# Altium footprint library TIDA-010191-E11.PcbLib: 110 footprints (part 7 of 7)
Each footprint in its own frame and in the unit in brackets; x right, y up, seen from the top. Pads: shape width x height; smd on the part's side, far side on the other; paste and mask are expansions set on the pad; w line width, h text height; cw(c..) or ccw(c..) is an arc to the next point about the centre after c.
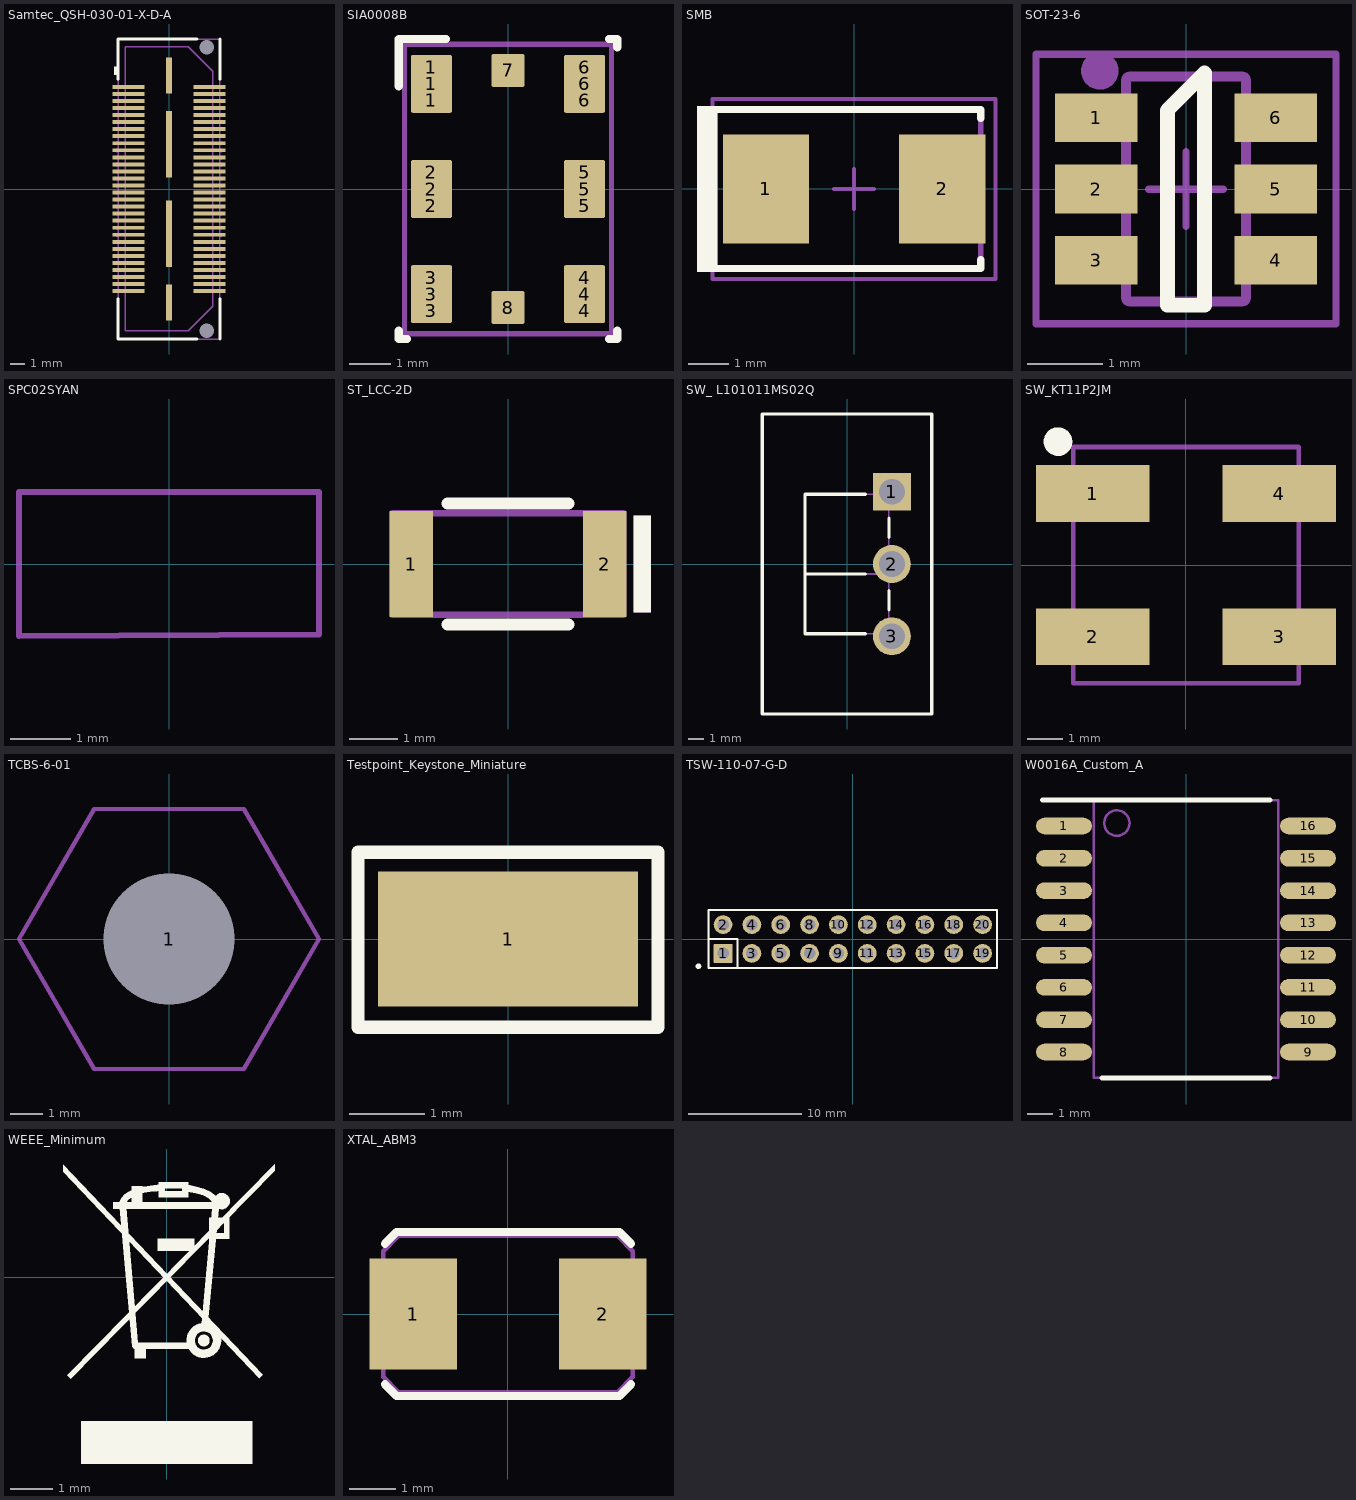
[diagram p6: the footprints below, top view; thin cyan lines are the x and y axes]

## Samtec_QSH-030-01-X-D-A [mm] "Receptacle, 0.5 mm, 30x2, TH"
height 3.327
pads (66):
  rect 2.27x0.279 smd: 1(-2.865,7.25) 2(2.865,7.25) 3(-2.865,6.75) 4(2.865,6.75) 5(-2.865,6.25) 6(2.865,6.25) 7(-2.865,5.75) 8(2.865,5.75) 9(-2.865,5.25) 10(2.865,5.25) 11(-2.865,4.75) 12(2.865,4.75) 13(-2.865,4.25) 14(2.865,4.25) 15(-2.865,3.75) 16(2.865,3.75) 17(-2.865,3.25) 18(2.865,3.25) 19(-2.865,2.75) 20(2.865,2.75) 21(-2.865,2.25) 22(2.865,2.25) 23(-2.865,1.75) 24(2.865,1.75) 25(-2.865,1.25) 26(2.865,1.25) 27(-2.865,0.75) 28(2.865,0.75) 29(-2.865,0.25) 30(2.865,0.25) 31(-2.865,-0.25) 32(2.865,-0.25) 33(-2.865,-0.75) 34(2.865,-0.75) 35(-2.865,-1.25) 36(2.865,-1.25) 37(-2.865,-1.75) 38(2.865,-1.75) 39(-2.865,-2.25) 40(2.865,-2.25) 41(-2.865,-2.75) 42(2.865,-2.75) 43(-2.865,-3.25) 44(2.865,-3.25) 45(-2.865,-3.75) 46(2.865,-3.75) 47(-2.865,-4.25) 48(2.865,-4.25) 49(-2.865,-4.75) 50(2.865,-4.75) 51(-2.865,-5.25) 52(2.865,-5.25) 53(-2.865,-5.75) 54(2.865,-5.75) 55(-2.865,-6.25) 56(2.865,-6.25) 57(-2.865,-6.75) 58(2.865,-6.75) 59(-2.865,-7.25) 60(2.865,-7.25)
  round 0 hole 1.02 unplated: MH1(2.67,10.065) MH2(2.67,-10.065)
  rect 0.43x2.54 smd: MP1(0,8.065) MP4(0,-8.065)
  rect 0.43x4.7 smd: MP2(0,3.175) MP3(0,-3.175)
Top Overlay:
  rectangle: -3.9,8.1 -3.62,8.7
  lines w0.2: -3.62,-7.789 -3.62,-10.655 2,-10.655 ; -3.62,7.789 -3.62,10.655 2,10.655 ; 3.62,-10.655 3.62,-7.789 ; 3.62,7.789 3.62,10.655
Mechanical 5:
  drawing of 190 lines, arcs and shapes, not listed
  text ".Designator" at -1.524,-0.508 h1.02
3D body "Samtec-QSH-030-01-L-D-A.stp": height 3.25, standoff -0.75, extent -3.746,-10.636 3.747,10.674

## SIA0008B [mm] "SIP 8-Leads, Body 5x7mm"
height 1.1
pads (20):
  rrect50% 1x0.6 on Top Paste: 1(-1.85,2.14) 1(-1.85,2.94) 2(-1.85,-0.4) 2(-1.85,0.4) 3(-1.85,-2.94) 3(-1.85,-2.14) 4(1.85,-2.94) 4(1.85,-2.14) 5(1.85,-0.4) 5(1.85,0.4) 6(1.85,2.14) 6(1.85,2.94)
  rrect10% 1x1.4 smd paste-0.5: 1(-1.85,2.54) 2(-1.85,0) 3(-1.85,-2.54) 4(1.85,-2.54) 5(1.85,0) 6(1.85,2.54)
  rrect12% 0.8x0.8 smd: 7(0,2.865) 8(0,-2.865)
Top Overlay:
  lines w0.2: -2.64,-3.425 -2.64,-3.625 -2.44,-3.625 ; -2.64,2.485 -2.64,3.625 -1.5,3.625 ; 2.44,-3.625 2.64,-3.625 2.64,-3.425 ; 2.44,3.625 2.64,3.625 2.64,3.425
Mechanical 5:
  circle w0.1: c-1.84,2.54 r0.25
  lines w0.127: -2.5,-3.5 2.5,-3.5 2.5,3.5 -2.5,3.5 -2.5,-3.5
  text ".Designator" at -1.4,0 h0.76
3D body: height 1.1, standoff 0, extent -2.564,-3.564 2.564,3.564
3D body: height 1.13, standoff 0, extent -2.156,2.224 -1.525,2.856

## SMB [mm] "Molded Diode, 2-Leads, Body 5.4x3.6mm, IPC Medium Density, based on OnSemi component dimensions"
height 2.65
pads (2):
  rect 2.159x2.743 smd: 1(-2.21,0) 2(2.21,0)
Top Overlay:
  rectangle: -3.937,-2.083 -3.429,2.083
  lines w0.178: -3.607,-1.994 3.175,-1.994 3.175,-1.765 ; -3.607,1.994 3.175,1.994 3.175,1.765
Mechanical 5:
  rectangle: -3.937,-2.083 -3.429,2.083
  lines w0.127: -3.607,-1.994 3.175,-1.994 3.175,-1.765 3.175,1.765 3.175,1.994 -3.607,1.994
  text ".Designator" at -2.311,-0.508 h1.02
Mechanical 15:
  lines w0.1: -0.5,0 0.5,0 ; 0,-0.5 0,0.5 ; -3.55,-2.25 -3.55,2.25 3.55,2.25 3.55,-2.25 -3.55,-2.25
3D body "SMB_nominal.stp": height 2.32, standoff 0.02, extent -2.7,-1.8 2.7,1.8

## SOT-23-6 [mm] "SOT23, 6-Leads, Body 3.0x1.7mm, Pitch 0.95mm, Lead Span 2.9mm, IPC Medium Density"
height 1
pads (6):
  rect 1.1x0.65 smd: 1(-1.2,0.95) 2(-1.2,0) 3(-1.2,-0.95) 4(1.2,-0.95) 5(1.2,0) 6(1.2,0.95)
Top Overlay:
  lines w0.2: -0.25,-1.55 -0.25,1.05 0.25,1.55 0.25,-1.55 -0.25,-1.55
Mechanical 5:
  circle w0.25: c-1.15,1.575 r0.125
  lines w0.127: -0.8,-1.45 ccw(c-0.75,-1.45) -0.75,-1.5 ; -0.8,-1.45 -0.8,-1.45 ; -0.8,-1.45 -0.8,-1.2 ; -0.8,-1.2 -0.8,-0.7 ; -0.8,-1.2 -0.812,-1.2 -1.109,-1.2 -1.166,-1.2 -1.265,-1.2 -1.5,-1.2 -1.5,-0.7 -1.265,-0.7 -1.166,-0.7 -1.109,-0.7 -0.812,-0.7 -0.8,-0.7 ; -0.8,-0.7 -0.8,-0.25 ; -0.8,-0.25 -0.8,0.25 ; -0.8,-0.25 -0.812,-0.25 -1.109,-0.25 -1.166,-0.25 -1.265,-0.25 -1.5,-0.25 -1.5,0.25 -1.265,0.25 -1.166,0.25 -1.109,0.25 -0.812,0.25 -0.8,0.25 ; -0.8,0.25 -0.8,0.7 ; -0.8,0.7 -0.8,1.2 ; -0.8,0.7 -0.812,0.7 -1.109,0.7 -1.166,0.7 -1.265,0.7 -1.5,0.7 -1.5,1.2 -1.265,1.2 -1.166,1.2 -1.109,1.2 -0.812,1.2 -0.8,1.2 ; -0.8,1.2 -0.8,1.45 ; -0.8,1.45 cw(c-0.75,1.45) -0.75,1.5 ; -0.8,1.45 -0.8,1.45 ; -0.75,-1.5 0.75,-1.5 ; -0.75,-1.5 -0.75,-1.5 ; -0.75,1.5 -0.75,1.5 ; -0.75,1.5 0.75,1.5 ; 0.75,-1.5 ccw(c0.75,-1.45) 0.8,-1.45 ; 0.75,-1.5 0.75,-1.5 ; 0.75,1.5 cw(c0.75,1.45) 0.8,1.45 ; 0.75,1.5 0.75,1.5 ; 0.8,-1.45 0.8,-1.45 ; 0.8,-1.45 0.8,-1.2 ; 0.8,-1.2 0.812,-1.2 1.109,-1.2 1.166,-1.2 1.265,-1.2 1.5,-1.2 1.5,-0.7 1.265,-0.7 1.166,-0.7 1.109,-0.7 0.812,-0.7 0.8,-0.7 ; 0.8,-1.2 0.8,-0.7 ; 0.8,-0.7 0.8,-0.25 ; 0.8,-0.25 0.8,0.25 ; 0.8,-0.25 0.812,-0.25 1.109,-0.25 1.166,-0.25 1.265,-0.25 1.5,-0.25 1.5,0.25 1.265,0.25 1.166,0.25 1.109,0.25 0.812,0.25 0.8,0.25 ; 0.8,0.25 0.8,0.7 ; 0.8,0.7 0.812,0.7 1.109,0.7 1.166,0.7 1.265,0.7 1.5,0.7 1.5,1.2 1.265,1.2 1.166,1.2 1.109,1.2 0.812,1.2 0.8,1.2 ; 0.8,0.7 0.8,1.2 ; 0.8,1.2 0.8,1.45 ; 0.8,1.45 0.8,1.45
  text ".Designator" at -0.3,1.2 h0.64
Mechanical 15:
  lines w0.1: -0.5,0 0.5,0 ; 0,-0.5 0,0.5 ; -2,-1.8 2,-1.8 2,1.8 -2,1.8 -2,-1.8
3D body "SOT23-6.stp": height 1.3, standoff 0, extent -1.5,-1.5 1.5,1.5

## SPC02SYAN [mil] "SULLINS"
height 256
pads (1):
  round 1 on Mech3: 0(0,0)
Mechanical 5:
  lines w4: -98.43,-47.24 -98.43,47.24 98.43,47.24 98.43,-46.26 -98.43,-47.24
3D body "Sullins_SPC02SYAN.stp": height 366, standoff 110, extent -98.49,-46.99 98.51,47

## ST_LCC-2D [mm] "ST Microelectronics"
height 2.2
pads (2):
  rect 0.9x2.2 smd: 1(-2,0) 2(2,0)
Top Overlay:
  region: 2.952,1 2.952,-1 2.602,-1 2.602,1
  lines w0.254: -1.25,-1.25 1.25,-1.25 ; -1.25,1.25 1.25,1.25
Mechanical 5:
  region: 2.952,1 2.952,-1 2.602,-1 2.602,1
  lines w0.127: -2.385,-1.05 2.385,-1.05 2.385,1.05 -2.385,1.05 -2.385,-1.041 ; 2.388,-0.356 cw(c2.388,0) 2.388,0.356
  text ".Designator" at -1.803,-0.432 h0.9
3D body: height 2, standoff 1, extent -2.4,0.925 -2.375,1.05
3D body: height 2, standoff 0, extent -2.373,-1.06 2.396,1.039
3D body: height 2.2, standoff 2, extent -2,-0.8 2,0.8
3D body: height 2, standoff 0, extent -2.286,-0.991 2.311,0.965
3D body: height 2, standoff 1, extent -2.4,-1.075 -2.375,-0.95

## SW_ L101011MS02Q [mm] "SWITCH SLIDE sPST 4A PCB"
height 14.18
pads (3):
  rect 2.416x2.416 hole 1.65: 1(2.857,4.6)
  round 2.416 hole 1.65: 2(2.857,0) 3(2.857,-4.6)
Top Overlay:
  lines w0.2: -5.405,9.55 5.395,9.55 5.395,-9.55 ; -5.395,9.55 -5.395,-9.55 5.405,-9.55 ; -2.668,-0.635 1.166,-0.635 ; 1.166,-4.445 -2.668,-4.445 -2.668,4.445 1.166,4.445 ; 2.668,-2.911 2.668,-1.689 ; 2.668,1.689 2.668,2.911
Mechanical 5:
  lines w0.1: -2.668,-0.635 -2.668,-4.445 2.668,-4.445 2.668,-0.635 ; -2.668,-0.635 -2.668,4.445 2.668,4.445 2.668,-0.635 ; -2.668,-0.635 2.668,-0.635 ; -5.395,-9.55 -5.395,9.55 5.395,9.55 5.395,-9.55 -5.395,-9.55
  text ".Designator" at -2,0.9 h1.02
3D body: height 9.1, standoff 0, extent -5.394,-9.549 5.394,9.549
3D body: height 14.18, standoff 9.1, extent -2.668,-0.635 2.668,4.445

## SW_KT11P2JM [mm] "C&K"
height 5.36
pads (4):
  rect 3.175x1.59 smd: 1(-2.602,2) 2(-2.602,-2) 3(2.603,-2) 4(2.603,2)
Top Overlay:
  circle w0.4: c-3.575,3.45 r0.2
Mechanical 5:
  lines w0.127: -3.15,-2.575 -3.825,-2.575 -3.825,-1.5 -3.15,-1.5 ; -3.15,1.5 -3.825,1.5 -3.825,2.575 -3.15,2.575 ; 3.15,-2.575 3.825,-2.575 3.825,-1.5 3.15,-1.5 ; 3.15,1.5 3.825,1.5 3.825,2.575 3.15,2.575 ; -3.15,-3.3 3.15,-3.3 3.15,3.3 -3.15,3.3 -3.15,-3.3
  text ".Designator" at -1.85,-0.5 h1.02
3D body: height 3, standoff 0, extent -2.999,-2.999 3,3
3D body: height 5.36, standoff 3, extent -1.852,-1.749 1.647,1.749

## TCBS-6-01 [mil] "Richco Plastics"
height 375
pads (1):
  round 60 hole 157 unplated: 1(0,0)
Mechanical 5:
  lines w5: -179.57,0 -89.79,155.51 89.78,155.51 179.56,0 89.78,-155.51 -89.79,-155.51 -179.57,0
  text ".Designator" at -60,-20 h40
3D body "Richco_TCBS-6.stp": height 374.61, standoff -387.57, extent -179.57,-155.51 179.56,155.52

## Testpoint_Keystone_Miniature [mil] "Miniature SMT test point"
height 90.55
pads (1):
  rect 135x70 smd: 1(0,0)
Top Overlay:
  lines w7: -78,-46 78,-46 78,45 5,45 -65,45 -78,45 -78,-38 -78,-46
Mechanical 5:
  lines w5: -78,-46 -78,-38 -78,45 -65,45 5,45 78,45 78,-46 -78,-46
  text ".Designator" at -60,-15 h40
3D body "keystone_5015.stp": height 60.6, standoff 0.6, extent -52.5,-20 52.5,20

## TSW-110-07-G-D [mm] "Samtec 100mil, 2x10, 230 mil above insulator"
height 8.382
pads (20):
  rrect6% 1.65x1.65 hole 1.016: 1(-11.43,-1.27)
  round 1.65 hole 1.016: 2(-11.43,1.27) 3(-8.89,-1.27) 4(-8.89,1.27) 5(-6.35,-1.27) 6(-6.35,1.27) 7(-3.81,-1.27) 8(-3.81,1.27) 9(-1.27,-1.27) 10(-1.27,1.27) 11(1.27,-1.27) 12(1.27,1.27) 13(3.81,-1.27) 14(3.81,1.27) 15(6.35,-1.27) 16(6.35,1.27) 17(8.89,-1.27) 18(8.89,1.27) 19(11.43,-1.27) 20(11.43,1.27)
Top Overlay:
  circle w0.25: c-13.6,-2.4 r0.125
  lines w0.178: -12.7,0 -10.16,0 -10.16,-2.54 ; -12.7,-2.54 -12.7,2.54 12.7,2.54 12.7,-2.54 -12.7,-2.54
Mechanical 5:
  rectangle: -11.938,-1.778 -10.922,-0.762
  lines w0.127: -12.7,-2.54 12.7,-2.54 12.7,2.54 -12.7,2.54 -12.7,-2.54
  text ".Designator" at -1.524,-0.508 h1.02
3D body "SamtecTSW-07_10x2.stp": height 8.38, standoff -2.54, extent -12.7,-2.54 12.7,2.54

## W0016A_Custom_A [mm] "DFP, 16 Leads, Body 10.2x6.7mm, Pitch 1.27mm, Gullwing Leadform"
height 2.03
pads (16):
  oval 2.2x0.65 smd: 1(-4.8,4.445) 2(-4.8,3.175) 3(-4.8,1.905) 4(-4.8,0.635) 5(-4.8,-0.635) 6(-4.8,-1.905) 7(-4.8,-3.175) 8(-4.8,-4.445) 9(4.8,-4.445) 10(4.8,-3.175) 11(4.8,-1.905) 12(4.8,-0.635) 13(4.8,0.635) 14(4.8,1.905) 15(4.8,3.175) 16(4.8,4.445)
Top Overlay:
  lines w0.2: -5.65,5.475 3.3,5.475 ; -3.3,-5.475 3.3,-5.475
Mechanical 5:
  circle w0.1: c-2.72,4.56 r0.5
  lines w0.1: -3.62,-5.46 -3.62,5.46 3.62,5.46 3.62,-5.46 -3.62,-5.46
  text ".Designator" at -0.875,5.275 h1.02
3D body: height 2.03, standoff 0.1, extent -3.62,-5.46 3.62,5.46

## WEEE_Minimum [mm] "WEEElie bin"
height 1.66
Top Overlay:
  drawing of 23 lines, arcs and shapes, not listed

## XTAL_ABM3 [mm] "Abracon recommended land pattern 12.28.10"
height 1.3
pads (2):
  rect 1.9x2.4 smd: 1(-2.05,0) 2(2.05,0)
Top Overlay:
  lines w0.178: -2.667,-1.524 -2.413,-1.778 0,-1.778 2.413,-1.778 2.667,-1.524 ; -2.667,1.524 -2.413,1.778 0,1.778 2.413,1.778 2.667,1.524
Mechanical 5:
  lines w0.1: -2.7,-1.364 -2.364,-1.7 2.364,-1.7 2.7,-1.364 2.7,1.364 2.364,1.7 -2.364,1.7 -2.7,1.364 -2.7,-1.364
  text ".Designator" at -1.778,-0.508 h1.02
3D body "Abracon_ABM3.stp": height 1.3, standoff 0, extent -2.597,-1.698 2.603,1.702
